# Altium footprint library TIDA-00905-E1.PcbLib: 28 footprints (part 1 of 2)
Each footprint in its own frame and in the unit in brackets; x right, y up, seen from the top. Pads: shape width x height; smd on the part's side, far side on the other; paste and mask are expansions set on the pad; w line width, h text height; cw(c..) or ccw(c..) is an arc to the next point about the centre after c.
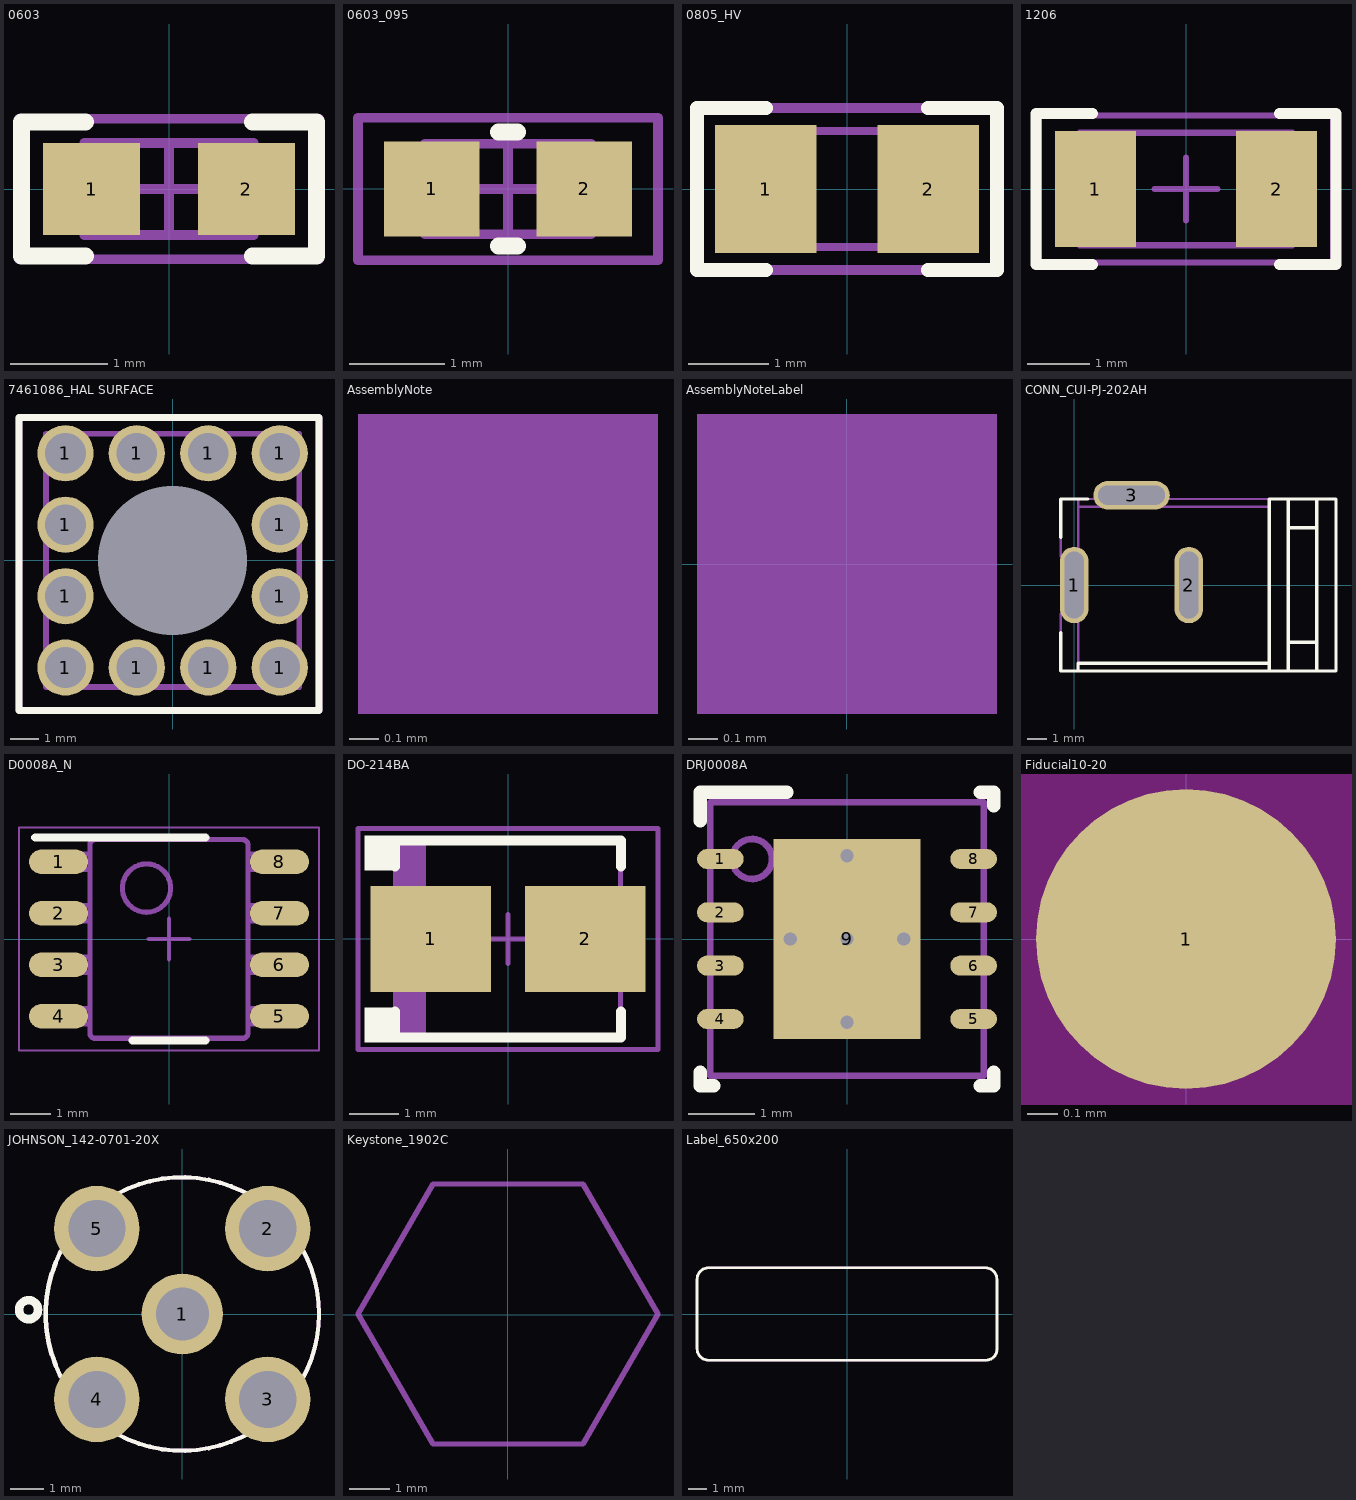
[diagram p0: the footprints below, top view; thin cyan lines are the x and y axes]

## 0603 [mm] "0603 from SM-752 data"
height 1
pads (2):
  rect 1x0.95 smd: 1(-0.8,0) 2(0.8,0)
Top Overlay:
  lines w0.178: -0.864,-0.691 -1.524,-0.691 -1.524,0.693 -0.864,0.693 ; 0.864,-0.691 1.524,-0.691 1.524,0.693 0.864,0.693
Mechanical 5:
  lines w0.1: -1.55,-0.725 1.55,-0.725 1.55,0.725 -1.55,0.725 -1.55,-0.725
  text ".Designator" at 0.985,0.341 h0.76
Mechanical 13:
  lines w0.1: -0.55,-0.475 -0.55,0.475 ; 0.55,-0.475 0.55,0.475 ; -0.875,-0.475 -0.875,0.475 0.875,0.475 0.875,-0.475 -0.875,-0.475
Mechanical 15:
  lines w0.1: -0.475,0 0.475,0 ; 0,-0.475 0,0.475 ; -1.55,-0.725 -1.55,0.725 1.55,0.725 1.55,-0.725 -1.55,-0.725
3D body: height 1, standoff 0, extent 0.551,-0.474 0.874,0.474
3D body: height 1, standoff 0, extent -0.549,-0.474 0.549,0.474
3D body: height 1, standoff 0, extent -0.874,-0.474 -0.551,0.474

## 0603_095 [mm] "0603_095"
height 0.95
pads (2):
  rect 1x1 smd: 1(-0.8,0) 2(0.8,0)
Top Overlay:
  lines w0.18: -0.1,-0.6 0.1,-0.6 ; -0.1,0.6 0.1,0.6
Mechanical 5:
  lines w0.1: -0.875,-0.475 -0.875,0.475 0.875,0.475 0.875,-0.475 -0.875,-0.475
  text ".Designator" at -2.653,-0.345 h0.76
Mechanical 15:
  lines w0.1: -0.475,0 0.475,0 ; 0,-0.475 0,0.475 ; -1.575,-0.75 -1.575,0.75 1.575,0.75 1.575,-0.75 -1.575,-0.75
3D body: height 0.95, standoff 0, extent -0.475,-0.475 0.475,0.475
3D body: height 0.95, standoff 0, extent -0.875,-0.475 -0.475,0.475
3D body: height 0.95, standoff 0, extent 0.475,-0.475 0.875,0.475

## 0805_HV [mil] "0805 with 30mil clearance between pads"
height 57.09
pads (2):
  rect 50x63 smd: 1(-40,0) 2(40,0)
Top Overlay:
  lines w7: -40,-40 -74,-40 -74,0 -74,40 -40,40 ; 40,-40 74,-40 74,0 74,40 40,40
Mechanical 5:
  lines w5: -74,-40 74,-40 74,40 -74,40 -74,-40
  text ".Designator" at 21,19 h30
Mechanical 13:
  lines w3.94: -25.59,-28.54 -25.59,28.54 ; 25.59,-28.54 25.59,28.54 ; -43.31,-28.54 43.31,-28.54 43.31,28.54 -43.31,28.54 -43.31,-28.54
3D body: height 57.09, standoff 0, extent -43.29,-28.52 -25.61,28.52
3D body: height 57.09, standoff 0, extent -25.57,-28.52 25.57,28.52
3D body: height 57.09, standoff 0, extent 25.61,-28.52 43.29,28.52

## 1206 [mm] "1206 from SM-752 data"
height 1.35
pads (2):
  rect 1.3x1.85 smd: 1(-1.45,0) 2(1.45,0)
Top Overlay:
  lines w0.178: -1.5,-1.21 -2.4,-1.21 -2.4,1.21 -1.5,1.21 ; 1.5,-1.21 2.4,-1.21 2.4,1.21 1.5,1.21
Mechanical 5:
  lines w0.1: -1.7,-0.9 -1.7,0.9 1.7,0.9 1.7,-0.9 -1.7,-0.9
  text ".Designator" at 1.016,0.254 h0.76
Mechanical 13:
  lines w0.1: -1.2,-0.9 -1.2,0.9 ; 1.2,-0.9 1.2,0.9 ; -1.7,-0.9 -1.7,0.9 1.7,0.9 1.7,-0.9 -1.7,-0.9
Mechanical 15:
  lines w0.1: -0.5,0 0.5,0 ; 0,-0.5 0,0.5 ; -2.35,-1.175 -2.35,1.175 2.35,1.175 2.35,-1.175 -2.35,-1.175
3D body: height 1.35, standoff 0, extent 1.201,-0.899 1.699,0.899
3D body: height 1.35, standoff 0, extent -1.199,-0.899 1.199,0.899
3D body: height 1.35, standoff 0, extent -1.699,-0.899 -1.201,0.899

## 7461086_HAL SURFACE [mm] "M4, thr 6mm"
height 9.5
pads (13):
  round 2 hole 1.45: 1(-3.81,-3.81) 1(-3.81,-1.27) 1(-3.81,1.27) 1(-3.81,3.81) 1(-1.27,-3.81) 1(-1.27,3.81) 1(1.27,-3.81) 1(1.27,3.81) 1(3.81,-3.81) 1(3.81,-1.27) 1(3.81,1.27) 1(3.81,3.81)
  round 0 hole 5.3 unplated: ""(0,0)
Top Overlay:
  lines w0.254: -5.461,-5.334 -5.461,5.08 5.207,5.08 5.207,-5.334 -5.461,-5.334
Mechanical 5:
  lines w0.254: -5.461,4.064 -5.461,5.08 5.207,5.08 5.207,-5.334 -5.461,-5.334 -5.461,4.445
  text ".Designator" at 0,0 h0.76
Mechanical 7:
  text "Sn 15um max." at -2.3,-5.5 h0.8
  text "Copper 25um-60um" at -2.9,-6.2 h0.8
Mechanical 13:
  lines w0.2: -4.5,-4.5 4.5,-4.5 4.5,4.5 -4.5,4.5 -4.5,-4.5
3D body: height 6.1, standoff -3.4, extent -4.5,-4.5 4.5,4.5

## AssemblyNote [mm] "Assembly Note"
Mechanical 5:
  rectangle: -34.798,-67.335 -33.782,-66.319
  text ".Comment" at -33.147,-67.335 h0.76
  text ".Designator" at -38.481,-67.335 h0.76

## AssemblyNoteLabel [mm] "Assembly Note for PCB Labels"
height 0.85
Mechanical 5:
  rectangle: -0.508,-0.508 0.508,0.508
  text "Install label in silkscreened box after final wash.  Text shall be 8 pt font.  Text shall be per the Label Table in the PDF schematic." at 1.143,-0.508 h0.76
  text ".Designator" at -4.191,-0.508 h0.76

## CONN_CUI-PJ-202AH [mm] "Conn_DC Jack"
height 11
pads (3):
  oval 1.5x4 hole 1 slot 3.5 at 90 deg: 1(0,0) 2(6,0)
  oval 4x1.5 hole 1 slot 3.5 at 0 deg: 3(3,4.7)
Top Overlay:
  lines w0.178: -0.7,-2.5 -0.7,-4.5 0.2,-4.5 ; -0.7,2.5 -0.7,4.5 0.2,4.5 0.7,4.5 ; 10.2,-4.1 0.2,-4.1 0.2,-4.5 ; 11.2,-3 12.7,-3 ; 11.2,3 12.7,3 ; 0.2,-4.5 10.2,-4.5 ; 10.2,-4.5 11.2,-4.5 ; 10.2,-4.5 10.2,4.5 11.2,4.5 ; 11.2,-4.5 11.2,4.5 ; 11.2,-4.5 12.7,-4.5 ; 11.2,4.5 12.7,4.5 ; 12.7,-4.5 12.7,4.5 ; 12.7,-4.5 13.7,-4.5 13.7,4.5 12.7,4.5
Mechanical 5:
  lines w0.127: 0.2,-1.5 -0.2,-1.5 ; 0.2,1.5 -0.2,1.5 ; 1.75,4.5 1.75,4.9 4.25,4.9 4.25,4.5 ; 10.2,-4.1 0.2,-4.1 ; 10.2,4.1 0.2,4.1 ; 11.2,-3 12.7,-3 ; 11.2,3 12.7,3 ; -0.2,-1.5 -0.2,1.5 ; -0.2,-1.5 -0.7,-1.5 -0.7,-4.5 0.2,-4.5 ; -0.2,1.5 -0.7,1.5 -0.7,4.5 0.2,4.5 ; 0.2,-4.5 10.2,-4.5 ; 0.2,-4.5 0.2,-4.1 ; 0.2,-4.1 0.2,4.1 ; 0.2,4.1 0.2,4.5 ; 0.2,4.5 10.2,4.5 ; 10.2,-4.5 10.2,4.5 ; 10.2,-4.5 11.2,-4.5 ; 10.2,4.5 11.2,4.5 ; 11.2,-4.5 12.7,-4.5 ; 11.2,-4.5 11.2,4.5 ; 11.2,4.5 12.7,4.5 ; 12.7,-4.5 13.7,-4.5 13.7,4.5 12.7,4.5 ; 12.7,-4.5 12.7,4.5
  text ".Designator" at 3.505,-0.381 h0.76
3D body: height 11.02, standoff -3.48, extent -0.7,-4.5 13.7,4.9

## D0008A_N [mm] "SOIC, 8-Leads, Body 4.9x3.9mm, Pitch 1.27mm, IPC Medium Density"
height 1.75
pads (8):
  oval 1.45x0.6 smd: 1(-2.725,1.905) 2(-2.725,0.635) 3(-2.725,-0.635) 4(-2.725,-1.905) 5(2.725,-1.905) 6(2.725,-0.635) 7(2.725,0.635) 8(2.725,1.905)
Top Overlay:
  lines w0.2: -3.3,2.5 0.9,2.5 ; -0.9,-2.5 0.9,-2.5
Mechanical 5:
  lines w0.127: -2.375,-2.095 -1.995,-2.095 -1.952,-2.095 -1.952,-1.715 -1.995,-1.715 -2.375,-1.715 ; -2.375,-2.095 -2.589,-2.095 -3.002,-2.095 -3.002,-1.715 -2.589,-1.715 -2.375,-1.715 ; -2.375,-2.095 -2.375,-1.715 ; -2.375,-0.825 -1.995,-0.825 -1.952,-0.825 -1.952,-0.445 -1.995,-0.445 -2.375,-0.445 ; -2.375,-0.825 -2.589,-0.825 -3.002,-0.825 -3.002,-0.445 -2.589,-0.445 -2.375,-0.445 ; -2.375,-0.825 -2.375,-0.445 ; -2.375,0.445 -1.995,0.445 -1.952,0.445 -1.952,0.825 -1.995,0.825 -2.375,0.825 ; -2.375,0.445 -2.589,0.445 -3.002,0.445 -3.002,0.825 -2.589,0.825 -2.375,0.825 ; -2.375,0.445 -2.375,0.825 ; -2.375,1.715 -1.995,1.715 -1.952,1.715 -1.952,2.095 -1.995,2.095 -2.375,2.095 ; -2.375,1.715 -2.589,1.715 -3.002,1.715 -3.002,2.095 -2.589,2.095 -2.375,2.095 ; -2.375,1.715 -2.375,2.095 ; -0.332,-2.45 -1.825,-2.45 -1.826,-2.45 cw(c-1.825,-2.323) -1.952,-2.324 -1.952,-2.323 -1.952,2.323 -1.952,2.324 cw(c-1.825,2.323) -1.826,2.45 -1.825,2.45 -0.332,2.45 ; -0.332,-2.45 -0.182,-2.45 ; -0.332,-2.45 -0.182,-2.45 ; -0.332,2.45 -0.182,2.45 ; -0.332,2.45 -0.182,2.45 ; -0.182,-2.45 0.178,-2.45 ; -0.182,2.45 0.178,2.45 ; 0.178,-2.45 0.328,-2.45 ; 0.178,-2.45 0.328,-2.45 ; 0.178,2.45 0.328,2.45 ; 0.178,2.45 0.328,2.45 ; 0.328,-2.45 1.821,-2.45 1.822,-2.45 ccw(c1.821,-2.323) 1.948,-2.324 1.948,-2.323 1.948,2.323 1.948,2.324 ccw(c1.821,2.323) 1.822,2.45 1.821,2.45 0.328,2.45 ; 2.371,-2.095 2.585,-2.095 2.998,-2.095 2.998,-1.715 2.585,-1.715 2.371,-1.715 ; 2.371,-2.095 1.991,-2.095 1.948,-2.095 1.948,-1.715 1.991,-1.715 2.371,-1.715 ; 2.371,-2.095 2.371,-1.715 ; 2.371,-0.825 2.585,-0.825 2.998,-0.825 2.998,-0.445 2.585,-0.445 2.371,-0.445 ; 2.371,-0.825 1.991,-0.825 1.948,-0.825 1.948,-0.445 1.991,-0.445 2.371,-0.445 ; 2.371,-0.825 2.371,-0.445 ; 2.371,0.445 2.585,0.445 2.998,0.445 2.998,0.825 2.585,0.825 2.371,0.825 ; 2.371,0.445 1.991,0.445 1.948,0.445 1.948,0.825 1.991,0.825 2.371,0.825 ; 2.371,0.445 2.371,0.825 ; 2.371,1.715 2.585,1.715 2.998,1.715 2.998,2.095 2.585,2.095 2.371,2.095 ; 2.371,1.715 1.991,1.715 1.948,1.715 1.948,2.095 1.991,2.095 2.371,2.095 ; 2.371,1.715 2.371,2.095 ; -0.555,0.659 cw(c-0.555,1.256) -0.555,1.853 cw(c-0.555,1.256) -0.555,0.659
  text ".Designator" at -0.208,0.191 h0.76
Mechanical 15:
  lines w0.05: -3.7,-2.75 3.7,-2.75 3.7,2.75 -3.7,2.75 -3.7,-2.75
  lines w0.1: -0.5,0 0.5,0 ; 0,-0.5 0,0.5
3D body: height 1.63, standoff 0, extent -3,-2.45 3,2.45

## DO-214BA [mm] "Molded Diode, 2-Leads, Body 4.3x3.6mm, IPC Medium Density"
height 3.3
pads (2):
  rect 2.45x2.15 smd: 1(-1.575,0) 2(1.575,0)
Top Overlay:
  rectangle: -2.921,-2.1 -2.3,-1.397
  rectangle: -2.921,1.397 -2.3,2.1
  lines w0.2: -2.3,-1.475 -2.3,-2 2.3,-2 2.3,-1.475 ; -2.3,1.475 -2.3,2 2.3,2 2.3,1.475
Mechanical 5:
  rectangle: -2.285,-1.97 -1.67,1.97
  lines w0.1: -2.285,-1.97 -2.285,1.97 2.285,1.97 2.285,-1.97 -2.285,-1.97
  text ".Designator" at 0.508,-0.559 h0.76
Mechanical 15:
  lines w0.1: -0.5,0 0.5,0 ; 0,-0.5 0,0.5 ; -3.05,-2.25 -3.05,2.25 3.05,2.25 3.05,-2.25 -3.05,-2.25
3D body: height 3.3, standoff 3.2, extent -1.904,-1.904 -1.398,1.904
3D body: height 3.3, standoff 0, extent -2.285,-1.97 2.285,1.97

## DRJ0008A [mm] "SON, 8-Leads, Body 4x4mm, Pitch 0.8mm, Thermal Pad 3x2.2mm, TI Recommended"
height 0.8
pads (9):
  oval 0.7x0.3 smd: 1(-1.9,1.2) 2(-1.9,0.4) 3(-1.9,-0.4) 4(-1.9,-1.2) 5(1.9,-1.2) 6(1.9,-0.4) 7(1.9,0.4) 8(1.9,1.2)
  rect 2.2x3 smd paste-1.1: 9(0,0)
via 0.85,0 diameter 0.5 hole 0.2
via 0,0 diameter 0.5 hole 0.2
via 0,1.25 diameter 0.5 hole 0.2
via 0,-1.25 diameter 0.5 hole 0.2
via -0.85,0 diameter 0.5 hole 0.2
Top Overlay:
  lines w0.2: -2.2,-2 -2.2,-2.2 -2,-2.2 ; -2.2,1.775 -2.2,2.2 -0.9,2.2 ; 2,-2.2 2.2,-2.2 2.2,-2 ; 2,2.2 2.2,2.2 2.2,2
Top Paste:
  rectangle: 0.098,0.1 1.079,1.41
  region: -0.102,1.41 -1.083,1.41 -1.083,0.1 -0.102,0.1
  region: -0.102,-0.1 -1.083,-0.1 -1.083,-1.41 -0.102,-1.41
  rectangle: 0.098,-1.41 1.079,-0.1
Mechanical 5:
  circle w0.1: c-1.425,1.2 r0.3
  lines w0.1: -2.05,-2.05 2.05,-2.05 2.05,2.05 -2.05,2.05 -2.05,-2.05
  text ".Designator" at -0.294,0.399 h0.76
3D body: height 0.8, standoff 0, extent -2.05,-2.05 2.05,2.05
3D body: height 0.81, standoff 0.5, extent -1.73,0.895 -1.12,1.505

## FCC_disclaimer [mm]
height 0.85
Bottom Overlay:
  text "For evaluation only; not FCC approved for resale." at 39.751,109.423 h1.52

## Fiducial10-20 [mm]
height 0.85
pads (1):
  round 1 smd mask+0.5: 1(0,0)
Top Layer keep-out:
  circle w1.178: c0,0 r0.5

## JOHNSON_142-0701-20X [mil] "Johnson Components recommended land pattern"
height 375
pads (5):
  round 95 hole 62: 1(0,0)
  round 100 hole 67: 2(100,100) 3(100,-100) 4(-100,-100) 5(-100,100)
Top Overlay:
  circle w5: c0,0 r160
  circle w10: c-180,5 r11.18
Mechanical 5:
  circle w5: c0,0 r160
  circle w10: c0,0 r15
  text ".Designator" at -15,-85 h30
3D body: height 375, standoff -155, extent -155.99,-155.8 156.01,155.8

## Keystone_1902C [mil] "Hex Standoff, 4-40 threaded, nylon"
height 500
pads (1):
  round 1 on Mech3: 0(0,0)
Mechanical 5:
  lines w5: -145.29,0.49 -72.56,-125.49 72.92,-125.49 145.65,0.49 72.92,126.47 -72.56,126.47 -145.29,0.49
  text ".Designator" at 7,-23 h30
3D body: height 501, standoff 1, extent -144.95,-125.98 146,125.98

## Label_650x200 [mil] "Thermal Transfer Label"
height 1
pads (1):
  round 1 on Mech13: 0(0,0)
Top Overlay:
  lines w6: -325,-75 ccw(c-300,-75) -300,-100 301.51,-100 ccw(c301.51,-76.51) 325,-76.51 325,75 ccw(c300,75) 300,100 -300,100 ccw(c-300,75) -325,75 -325,-75
Mechanical 5:
  lines w5: -325,-75 ccw(c-300,-75) -300,-100 300,-100 ccw(c300,-75) 325,-75 325,75 ccw(c300,75) 300,100 -300,100 ccw(c-300,75) -325,75 -325,-75
  text ".Designator" at 18,12 h30
3D body: height 1, standoff 0, extent -325.51,-100.51 325.51,100.51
